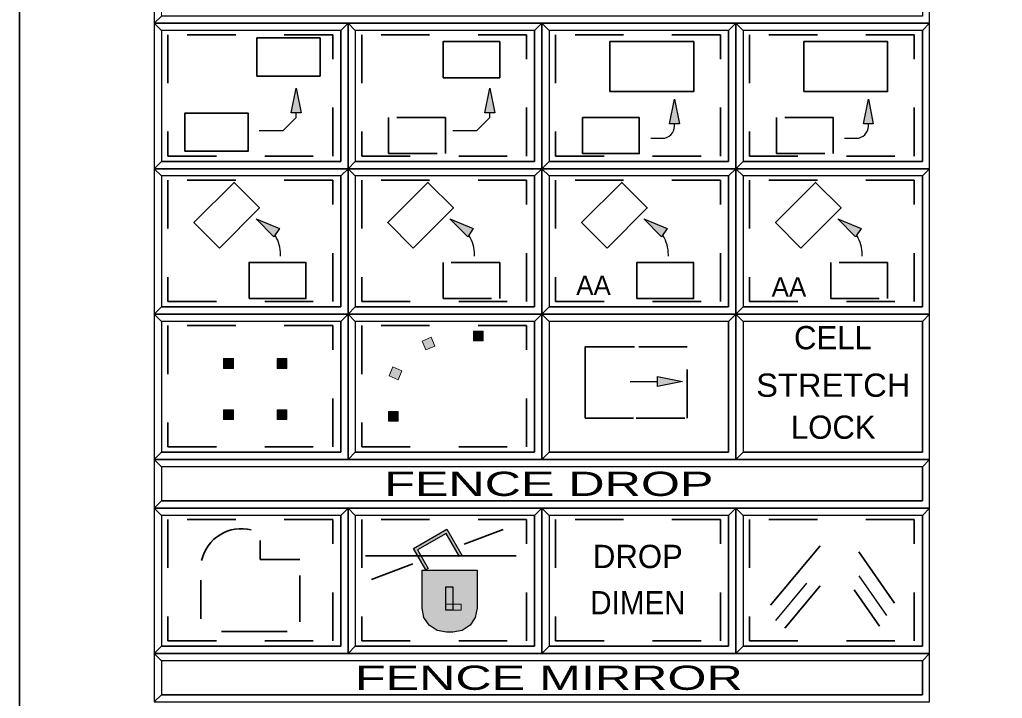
# Model space of a CAD drawing. Extents: x 95906.9 to 95918.9, y 90964.8 to 90972.9.
# Drawn here: x 95906.855 to 95908.882, y 90966.169 to 90967.569 of the extents above; entities that cross this region are included whole.
import ezdxf
from ezdxf.enums import TextEntityAlignment as Align

# ---------------------------------------------------------------- set-up
doc = ezdxf.new("R2010")
doc.units = 0
doc.header["$LTSCALE"] = 0.019
for name, pattern in [('DOT_DASHED', [7.7, 5, -1.2, 0.3, -1.2]), ('DOTTED', [1.5, 0.3, -1.2]), ('MEDIUM_DASHED', [4.5, 3, -1.5])]:
    doc.linetypes.add(name, pattern=pattern)
for name, color, linetype, lineweight in [('1', 7, 'Continuous', 25), ('11', 7, 'Continuous', 25), ('12', 7, 'Continuous', 25), ('18', 7, 'Continuous', 25), ('2', 7, 'Continuous', 13), ('3', 7, 'Continuous', 25), ('4', 7, 'Continuous', 35), ('6', 7, 'Continuous', 35), ('7', 7, 'Continuous', 35)]:
    doc.layers.add(name, color=color, linetype=linetype, lineweight=lineweight)

msp = doc.modelspace()

# ---------------------------------------------------------------- hatches: boundary and pattern name
at = {"layer": '6'}
for points in [[(95907.4251, 90967.4281), (95907.4353, 90967.3769), (95907.4149, 90967.3769)], [(95907.8251, 90967.4281), (95907.8353, 90967.3769), (95907.8149, 90967.3769)], [(95908.2059, 90967.4052), (95908.2161, 90967.354), (95908.1957, 90967.354)], [(95908.6059, 90967.4052), (95908.6161, 90967.354), (95908.5957, 90967.354)], [(95907.3426, 90967.1585), (95907.3908, 90967.1384), (95907.3793, 90967.1214)], [(95907.7426, 90967.1585), (95907.7908, 90967.1384), (95907.7793, 90967.1214)], [(95908.1426, 90967.1585), (95908.1908, 90967.1384), (95908.1793, 90967.1214)], [(95908.5426, 90967.1585), (95908.5908, 90967.1384), (95908.5793, 90967.1214)], [(95907.7115, 90966.8955), (95907.7038, 90966.914), (95907.6854, 90966.9063), (95907.693, 90966.8878)], [(95907.7912, 90966.9067), (95907.8112, 90966.9067), (95907.8112, 90966.9267), (95907.7912, 90966.9267)], [(95907.2757, 90966.8499), (95907.2957, 90966.8499), (95907.2957, 90966.8699), (95907.2757, 90966.8699)], [(95907.3861, 90966.8499), (95907.4061, 90966.8499), (95907.4061, 90966.8699), (95907.3861, 90966.8699)], [(95907.6432, 90966.845), (95907.6247, 90966.8527), (95907.6171, 90966.8342), (95907.6355, 90966.8265)], [(95908.2221, 90966.823), (95908.1709, 90966.8128), (95908.1709, 90966.8332)], [(95907.2757, 90966.7446), (95907.2957, 90966.7446), (95907.2957, 90966.7646), (95907.2757, 90966.7646)], [(95907.3861, 90966.7446), (95907.4061, 90966.7446), (95907.4061, 90966.7646), (95907.3861, 90966.7646)], [(95907.636, 90966.7408), (95907.636, 90966.7608), (95907.616, 90966.7608), (95907.616, 90966.7408)], [(95907.693, 90966.4345), (95907.6677, 90966.4783), (95907.7363, 90966.5179), (95907.767, 90966.4648), (95907.7623, 90966.4621), (95907.7351, 90966.5095), (95907.6755, 90966.4753), (95907.6975, 90966.4371)], [(95907.6852, 90966.3554), (95907.6852, 90966.4338), (95907.7987, 90966.4338), (95907.7987, 90966.3554), (95907.7949, 90966.3363), (95907.7841, 90966.32), (95907.7678, 90966.3092), (95907.7487, 90966.3054), (95907.7352, 90966.3054), (95907.7161, 90966.3092), (95907.6998, 90966.32), (95907.689, 90966.3363)], [(95907.7342, 90966.3989), (95907.7484, 90966.3989), (95907.7484, 90966.3508), (95907.7342, 90966.3508)], [(95907.7342, 90966.3508), (95907.7655, 90966.3508), (95907.7655, 90966.3633), (95907.7342, 90966.3633)]]:
    msp.add_hatch(color=256, dxfattribs=at).paths.add_polyline_path(points)

# ---------------------------------------------------------------- linework, layer by layer
at = {"layer": '1'}
for points in [[(95907.1323, 90967.5617), (95908.7323, 90967.5617), (95908.7323, 90967.6617), (95907.1323, 90967.6617)], [(95907.1323, 90967.2617), (95907.5323, 90967.2617), (95907.5323, 90967.5617), (95907.1323, 90967.5617)], [(95907.5323, 90967.2617), (95907.9323, 90967.2617), (95907.9323, 90967.5617), (95907.5323, 90967.5617)], [(95907.9323, 90967.2617), (95908.3323, 90967.2617), (95908.3323, 90967.5617), (95907.9323, 90967.5617)], [(95908.3323, 90967.2617), (95908.7323, 90967.2617), (95908.7323, 90967.5617), (95908.3323, 90967.5617)], [(95907.1323, 90966.9617), (95907.5323, 90966.9617), (95907.5323, 90967.2617), (95907.1323, 90967.2617)], [(95907.5323, 90966.9617), (95907.9323, 90966.9617), (95907.9323, 90967.2617), (95907.5323, 90967.2617)], [(95907.9323, 90966.9617), (95908.3323, 90966.9617), (95908.3323, 90967.2617), (95907.9323, 90967.2617)], [(95908.3323, 90966.9617), (95908.7323, 90966.9617), (95908.7323, 90967.2617), (95908.3323, 90967.2617)], [(95907.1323, 90966.6617), (95907.5323, 90966.6617), (95907.5323, 90966.9617), (95907.1323, 90966.9617)], [(95907.5323, 90966.6617), (95907.9323, 90966.6617), (95907.9323, 90966.9617), (95907.5323, 90966.9617)], [(95907.9323, 90966.6617), (95908.3323, 90966.6617), (95908.3323, 90966.9617), (95907.9323, 90966.9617)], [(95908.3323, 90966.6617), (95908.7323, 90966.6617), (95908.7323, 90966.9617), (95908.3323, 90966.9617)], [(95907.1323, 90966.5617), (95908.7323, 90966.5617), (95908.7323, 90966.6617), (95907.1323, 90966.6617)], [(95907.1323, 90966.2617), (95907.5323, 90966.2617), (95907.5323, 90966.5617), (95907.1323, 90966.5617)], [(95907.5323, 90966.2617), (95907.9323, 90966.2617), (95907.9323, 90966.5617), (95907.5323, 90966.5617)], [(95907.9323, 90966.2617), (95908.3323, 90966.2617), (95908.3323, 90966.5617), (95907.9323, 90966.5617)], [(95908.3323, 90966.2617), (95908.7323, 90966.2617), (95908.7323, 90966.5617), (95908.3323, 90966.5617)], [(95907.1323, 90966.1617), (95908.7323, 90966.1617), (95908.7323, 90966.2617), (95907.1323, 90966.2617)]]:
    msp.add_lwpolyline(points, close=True, dxfattribs=at)
at = {"layer": '11'}
for points in [[(95907.1473, 90967.2767), (95907.5173, 90967.2767), (95907.5173, 90967.5467), (95907.1473, 90967.5467)], [(95907.5473, 90967.2767), (95907.9173, 90967.2767), (95907.9173, 90967.5467), (95907.5473, 90967.5467)], [(95907.9473, 90967.2767), (95908.3173, 90967.2767), (95908.3173, 90967.5467), (95907.9473, 90967.5467)], [(95908.3473, 90967.2767), (95908.7173, 90967.2767), (95908.7173, 90967.5467), (95908.3473, 90967.5467)], [(95907.1473, 90966.9767), (95907.5173, 90966.9767), (95907.5173, 90967.2467), (95907.1473, 90967.2467)], [(95907.5473, 90966.9767), (95907.9173, 90966.9767), (95907.9173, 90967.2467), (95907.5473, 90967.2467)], [(95907.9473, 90966.9767), (95908.3173, 90966.9767), (95908.3173, 90967.2467), (95907.9473, 90967.2467)], [(95908.3473, 90966.9767), (95908.7173, 90966.9767), (95908.7173, 90967.2467), (95908.3473, 90967.2467)], [(95907.1473, 90966.6767), (95907.5173, 90966.6767), (95907.5173, 90966.9467), (95907.1473, 90966.9467)], [(95907.5473, 90966.6767), (95907.9173, 90966.6767), (95907.9173, 90966.9467), (95907.5473, 90966.9467)], [(95907.9473, 90966.6767), (95908.3173, 90966.6767), (95908.3173, 90966.9467), (95907.9473, 90966.9467)], [(95908.3473, 90966.6767), (95908.7173, 90966.6767), (95908.7173, 90966.9467), (95908.3473, 90966.9467)], [(95907.1473, 90966.2767), (95907.5173, 90966.2767), (95907.5173, 90966.5467), (95907.1473, 90966.5467)], [(95907.5473, 90966.2767), (95907.9173, 90966.2767), (95907.9173, 90966.5467), (95907.5473, 90966.5467)], [(95907.9473, 90966.2767), (95908.3173, 90966.2767), (95908.3173, 90966.5467), (95907.9473, 90966.5467)], [(95908.3473, 90966.2767), (95908.7173, 90966.2767), (95908.7173, 90966.5467), (95908.3473, 90966.5467)]]:
    msp.add_lwpolyline(points, close=True, dxfattribs=at)
at = {"layer": '12'}
msp.add_lwpolyline([(95907.1473, 90966.2767), (95907.5173, 90966.2767), (95907.5173, 90966.5467), (95907.1473, 90966.5467)], close=True, dxfattribs=at)
at = {"layer": '18'}
for points in [[(95907.1473, 90966.5767), (95908.7173, 90966.5767), (95908.7173, 90966.6467), (95907.1473, 90966.6467)], [(95907.1473, 90966.1767), (95908.7173, 90966.1767), (95908.7173, 90966.2467), (95907.1473, 90966.2467)]]:
    msp.add_lwpolyline(points, close=True, dxfattribs=at)
at = {"layer": '2'}
for points in [[(95907.1323, 90967.6617), (95907.1323, 90967.5617), (95907.1473, 90967.5767), (95907.1473, 90967.6467), (95908.7173, 90967.6467), (95908.7323, 90967.6617)], [(95907.1323, 90967.5617), (95907.1323, 90967.2617), (95907.1473, 90967.2767), (95907.1473, 90967.5467), (95907.5173, 90967.5467), (95907.5323, 90967.5617)], [(95907.5323, 90967.5617), (95907.5323, 90967.2617), (95907.5473, 90967.2767), (95907.5473, 90967.5467), (95907.9173, 90967.5467), (95907.9323, 90967.5617)], [(95907.9323, 90967.5617), (95907.9323, 90967.2617), (95907.9473, 90967.2767), (95907.9473, 90967.5467), (95908.3173, 90967.5467), (95908.3323, 90967.5617)], [(95908.3323, 90967.5617), (95908.3323, 90967.2617), (95908.3473, 90967.2767), (95908.3473, 90967.5467), (95908.7173, 90967.5467), (95908.7323, 90967.5617)], [(95907.1323, 90967.2617), (95907.1323, 90966.9617), (95907.1473, 90966.9767), (95907.1473, 90967.2467), (95907.5173, 90967.2467), (95907.5323, 90967.2617)], [(95907.5323, 90967.2617), (95907.5323, 90966.9617), (95907.5473, 90966.9767), (95907.5473, 90967.2467), (95907.9173, 90967.2467), (95907.9323, 90967.2617)], [(95907.9323, 90967.2617), (95907.9323, 90966.9617), (95907.9473, 90966.9767), (95907.9473, 90967.2467), (95908.3173, 90967.2467), (95908.3323, 90967.2617)], [(95908.3323, 90967.2617), (95908.3323, 90966.9617), (95908.3473, 90966.9767), (95908.3473, 90967.2467), (95908.7173, 90967.2467), (95908.7323, 90967.2617)], [(95907.1323, 90966.9617), (95907.1323, 90966.6617), (95907.1473, 90966.6767), (95907.1473, 90966.9467), (95907.5173, 90966.9467), (95907.5323, 90966.9617)], [(95907.5323, 90966.9617), (95907.5323, 90966.6617), (95907.5473, 90966.6767), (95907.5473, 90966.9467), (95907.9173, 90966.9467), (95907.9323, 90966.9617)], [(95907.9323, 90966.9617), (95907.9323, 90966.6617), (95907.9473, 90966.6767), (95907.9473, 90966.9467), (95908.3173, 90966.9467), (95908.3323, 90966.9617)], [(95908.3323, 90966.9617), (95908.3323, 90966.6617), (95908.3473, 90966.6767), (95908.3473, 90966.9467), (95908.7173, 90966.9467), (95908.7323, 90966.9617)], [(95907.1323, 90966.6617), (95907.1323, 90966.5617), (95907.1473, 90966.5767), (95907.1473, 90966.6467), (95908.7173, 90966.6467), (95908.7323, 90966.6617)], [(95907.1323, 90966.5617), (95907.1323, 90966.2617), (95907.1473, 90966.2767), (95907.1473, 90966.5467), (95907.5173, 90966.5467), (95907.5323, 90966.5617)], [(95907.5323, 90966.5617), (95907.5323, 90966.2617), (95907.5473, 90966.2767), (95907.5473, 90966.5467), (95907.9173, 90966.5467), (95907.9323, 90966.5617)], [(95907.9323, 90966.5617), (95907.9323, 90966.2617), (95907.9473, 90966.2767), (95907.9473, 90966.5467), (95908.3173, 90966.5467), (95908.3323, 90966.5617)], [(95908.3323, 90966.5617), (95908.3323, 90966.2617), (95908.3473, 90966.2767), (95908.3473, 90966.5467), (95908.7173, 90966.5467), (95908.7323, 90966.5617)], [(95907.1323, 90966.2617), (95907.1323, 90966.1617), (95907.1473, 90966.1767), (95907.1473, 90966.2467), (95908.7173, 90966.2467), (95908.7323, 90966.2617)]]:
    msp.add_lwpolyline(points, close=True, dxfattribs=at)
at = {"layer": '3'}
for points in [[(95907.1323, 90967.5617), (95908.7323, 90967.5617), (95908.7323, 90967.6617), (95908.7173, 90967.6467), (95908.7173, 90967.5767), (95907.1473, 90967.5767)], [(95907.1323, 90967.2617), (95907.5323, 90967.2617), (95907.5323, 90967.5617), (95907.5173, 90967.5467), (95907.5173, 90967.2767), (95907.1473, 90967.2767)], [(95907.5323, 90967.2617), (95907.9323, 90967.2617), (95907.9323, 90967.5617), (95907.9173, 90967.5467), (95907.9173, 90967.2767), (95907.5473, 90967.2767)], [(95907.9323, 90967.2617), (95908.3323, 90967.2617), (95908.3323, 90967.5617), (95908.3173, 90967.5467), (95908.3173, 90967.2767), (95907.9473, 90967.2767)], [(95908.3323, 90967.2617), (95908.7323, 90967.2617), (95908.7323, 90967.5617), (95908.7173, 90967.5467), (95908.7173, 90967.2767), (95908.3473, 90967.2767)], [(95907.1323, 90966.9617), (95907.5323, 90966.9617), (95907.5323, 90967.2617), (95907.5173, 90967.2467), (95907.5173, 90966.9767), (95907.1473, 90966.9767)], [(95907.5323, 90966.9617), (95907.9323, 90966.9617), (95907.9323, 90967.2617), (95907.9173, 90967.2467), (95907.9173, 90966.9767), (95907.5473, 90966.9767)], [(95907.9323, 90966.9617), (95908.3323, 90966.9617), (95908.3323, 90967.2617), (95908.3173, 90967.2467), (95908.3173, 90966.9767), (95907.9473, 90966.9767)], [(95908.3323, 90966.9617), (95908.7323, 90966.9617), (95908.7323, 90967.2617), (95908.7173, 90967.2467), (95908.7173, 90966.9767), (95908.3473, 90966.9767)], [(95907.1323, 90966.6617), (95907.5323, 90966.6617), (95907.5323, 90966.9617), (95907.5173, 90966.9467), (95907.5173, 90966.6767), (95907.1473, 90966.6767)], [(95907.5323, 90966.6617), (95907.9323, 90966.6617), (95907.9323, 90966.9617), (95907.9173, 90966.9467), (95907.9173, 90966.6767), (95907.5473, 90966.6767)], [(95907.9323, 90966.6617), (95908.3323, 90966.6617), (95908.3323, 90966.9617), (95908.3173, 90966.9467), (95908.3173, 90966.6767), (95907.9473, 90966.6767)], [(95908.3323, 90966.6617), (95908.7323, 90966.6617), (95908.7323, 90966.9617), (95908.7173, 90966.9467), (95908.7173, 90966.6767), (95908.3473, 90966.6767)], [(95907.1323, 90966.5617), (95908.7323, 90966.5617), (95908.7323, 90966.6617), (95908.7173, 90966.6467), (95908.7173, 90966.5767), (95907.1473, 90966.5767)], [(95907.1323, 90966.2617), (95907.5323, 90966.2617), (95907.5323, 90966.5617), (95907.5173, 90966.5467), (95907.5173, 90966.2767), (95907.1473, 90966.2767)], [(95907.5323, 90966.2617), (95907.9323, 90966.2617), (95907.9323, 90966.5617), (95907.9173, 90966.5467), (95907.9173, 90966.2767), (95907.5473, 90966.2767)], [(95907.9323, 90966.2617), (95908.3323, 90966.2617), (95908.3323, 90966.5617), (95908.3173, 90966.5467), (95908.3173, 90966.2767), (95907.9473, 90966.2767)], [(95908.3323, 90966.2617), (95908.7323, 90966.2617), (95908.7323, 90966.5617), (95908.7173, 90966.5467), (95908.7173, 90966.2767), (95908.3473, 90966.2767)], [(95907.1323, 90966.1617), (95908.7323, 90966.1617), (95908.7323, 90966.2617), (95908.7173, 90966.2467), (95908.7173, 90966.1767), (95907.1473, 90966.1767)]]:
    msp.add_lwpolyline(points, close=True, dxfattribs=at)
at = {"layer": '4'}
for p, q in [((95907.1473, 90967.5467), (95907.1323, 90967.5617)), ((95907.5473, 90967.5467), (95907.5323, 90967.5617)), ((95907.9473, 90967.5467), (95907.9323, 90967.5617)), ((95908.3473, 90967.5467), (95908.3323, 90967.5617)), ((95907.1473, 90967.2467), (95907.1323, 90967.2617)), ((95907.5473, 90967.2467), (95907.5323, 90967.2617)), ((95907.9473, 90967.2467), (95907.9323, 90967.2617)), ((95908.3473, 90967.2467), (95908.3323, 90967.2617)), ((95907.1473, 90966.9467), (95907.1323, 90966.9617)), ((95907.5473, 90966.9467), (95907.5323, 90966.9617)), ((95907.9473, 90966.9467), (95907.9323, 90966.9617)), ((95908.3473, 90966.9467), (95908.3323, 90966.9617)), ((95907.1473, 90966.6467), (95907.1323, 90966.6617)), ((95907.1473, 90966.5467), (95907.1323, 90966.5617)), ((95907.5473, 90966.5467), (95907.5323, 90966.5617)), ((95907.9473, 90966.5467), (95907.9323, 90966.5617)), ((95908.3473, 90966.5467), (95908.3323, 90966.5617)), ((95907.1473, 90966.2467), (95907.1323, 90966.2617))]:
    msp.add_line(p, q, dxfattribs=at)
at = {"layer": '6', "lineweight": 25}
for p, q in [((95907.4353, 90967.3769), (95907.4149, 90967.3769)), ((95907.8353, 90967.3769), (95907.8149, 90967.3769)), ((95908.2059, 90967.3495), (95908.2059, 90967.354)), ((95908.6059, 90967.3495), (95908.6059, 90967.354)), ((95908.1569, 90967.3245), (95908.1809, 90967.3245)), ((95908.5569, 90967.3245), (95908.5809, 90967.3245)), ((95907.3933, 90967.081), (95907.3933, 90967.0844)), ((95907.7933, 90967.081), (95907.7933, 90967.0844)), ((95908.1933, 90967.081), (95908.1933, 90967.0844)), ((95908.1933, 90967.081), (95908.1933, 90967.0844)), ((95908.5933, 90967.081), (95908.5933, 90967.0844)), ((95908.5933, 90967.081), (95908.5933, 90967.0844)), ((95908.1146, 90966.823), (95908.1709, 90966.823))]:
    msp.add_line(p, q, dxfattribs=at)
at = {"layer": '6'}
for p, q in [((95907.8521, 90966.5178), (95907.7717, 90966.4871)), ((95908.404, 90966.3615), (95908.5067, 90966.4839)), ((95908.5862, 90966.4713), (95908.6601, 90966.3657)), ((95907.5685, 90966.4635), (95907.8792, 90966.4635)), ((95907.5804, 90966.4142), (95907.6662, 90966.4469)), ((95907.2284, 90966.3332), (95907.2284, 90966.4131)), ((95907.4328, 90966.4223), (95907.4328, 90966.327)), ((95908.4335, 90966.3142), (95908.5067, 90966.4015)), ((95908.5763, 90966.3931), (95908.629, 90966.3178)), ((95907.4067, 90966.3071), (95907.2714, 90966.3071))]:
    msp.add_line(p, q, dxfattribs=at)
at = {"layer": '6', "linetype": 'DOT_DASHED', "lineweight": 25}
for p, q in [((95908.4147, 90966.3299), (95908.5067, 90966.4396)), ((95908.5862, 90966.4217), (95908.6491, 90966.3319))]:
    msp.add_line(p, q, dxfattribs=at)
at = {"layer": '6', "linetype": 'DOTTED'}
for points in [[(95907.5007, 90967.5382), (95907.1606, 90967.5382), (95907.1606, 90967.2878), (95907.5007, 90967.2878)], [(95907.9007, 90967.5382), (95907.5606, 90967.5382), (95907.5606, 90967.2878), (95907.9007, 90967.2878)], [(95908.3007, 90967.5382), (95907.9606, 90967.5382), (95907.9606, 90967.2878), (95908.3007, 90967.2878)], [(95908.7007, 90967.5382), (95908.3606, 90967.5382), (95908.3606, 90967.2878), (95908.7007, 90967.2878)], [(95907.5007, 90967.2382), (95907.1606, 90967.2382), (95907.1606, 90966.9878), (95907.5007, 90966.9878)], [(95907.9007, 90967.2382), (95907.5606, 90967.2382), (95907.5606, 90966.9878), (95907.9007, 90966.9878)], [(95908.3007, 90967.2382), (95907.9606, 90967.2382), (95907.9606, 90966.9878), (95908.3007, 90966.9878)], [(95908.7007, 90967.2382), (95908.3606, 90967.2382), (95908.3606, 90966.9878), (95908.7007, 90966.9878)], [(95907.5007, 90966.9382), (95907.1606, 90966.9382), (95907.1606, 90966.6878), (95907.5007, 90966.6878)], [(95907.9007, 90966.9382), (95907.5606, 90966.9382), (95907.5606, 90966.6878), (95907.9007, 90966.6878)], [(95907.5007, 90966.5382), (95907.1606, 90966.5382), (95907.1606, 90966.2878), (95907.5007, 90966.2878)], [(95907.9007, 90966.5382), (95907.5606, 90966.5382), (95907.5606, 90966.2878), (95907.9007, 90966.2878)], [(95908.3007, 90966.5382), (95907.9606, 90966.5382), (95907.9606, 90966.2878), (95908.3007, 90966.2878)], [(95908.7007, 90966.5382), (95908.3606, 90966.5382), (95908.3606, 90966.2878), (95908.7007, 90966.2878)]]:
    msp.add_lwpolyline(points, close=True, dxfattribs=at)
at = {"layer": '6'}
for points in [[(95907.3442, 90967.4528), (95907.4747, 90967.4528), (95907.4747, 90967.5315), (95907.3442, 90967.5315)], [(95907.7284, 90967.4495), (95907.8455, 90967.4495), (95907.8455, 90967.5238), (95907.7284, 90967.5238)], [(95908.0724, 90967.421), (95908.2455, 90967.421), (95908.2455, 90967.5238), (95908.0724, 90967.5238)], [(95908.4724, 90967.421), (95908.6455, 90967.421), (95908.6455, 90967.5238), (95908.4724, 90967.5238)], [(95907.1957, 90967.2977), (95907.3262, 90967.2977), (95907.3262, 90967.3764), (95907.1957, 90967.3764)], [(95908.0161, 90967.2929), (95908.1332, 90967.2929), (95908.1332, 90967.3672), (95908.0161, 90967.3672)], [(95907.2668, 90967.0981), (95907.3496, 90967.1809), (95907.2971, 90967.2334), (95907.2143, 90967.1506)], [(95907.6668, 90967.0981), (95907.7496, 90967.1809), (95907.6971, 90967.2334), (95907.6143, 90967.1506)], [(95908.0668, 90967.0981), (95908.1496, 90967.1809), (95908.0971, 90967.2334), (95908.0143, 90967.1506)], [(95908.4668, 90967.0981), (95908.5496, 90967.1809), (95908.4971, 90967.2334), (95908.4143, 90967.1506)], [(95907.3283, 90966.994), (95907.4454, 90966.994), (95907.4454, 90967.0683), (95907.3283, 90967.0683)], [(95908.1283, 90966.994), (95908.2454, 90966.994), (95908.2454, 90967.0683), (95908.1283, 90967.0683)]]:
    msp.add_lwpolyline(points, close=True, dxfattribs=at)
at = {"layer": '6', "lineweight": 25}
for points in [[(95907.4251, 90967.4281), (95907.4353, 90967.3769), (95907.4149, 90967.3769)], [(95907.8251, 90967.4281), (95907.8353, 90967.3769), (95907.8149, 90967.3769)], [(95908.2059, 90967.4052), (95908.2161, 90967.354), (95908.1957, 90967.354)], [(95908.6059, 90967.4052), (95908.6161, 90967.354), (95908.5957, 90967.354)], [(95907.3426, 90967.1585), (95907.3908, 90967.1384), (95907.3793, 90967.1214)], [(95907.7426, 90967.1585), (95907.7908, 90967.1384), (95907.7793, 90967.1214)], [(95908.1426, 90967.1585), (95908.1908, 90967.1384), (95908.1793, 90967.1214)], [(95908.5426, 90967.1585), (95908.5908, 90967.1384), (95908.5793, 90967.1214)], [(95908.2221, 90966.823), (95908.1709, 90966.8128), (95908.1709, 90966.8332)], [(95907.693, 90966.4345), (95907.6677, 90966.4783), (95907.7363, 90966.5179), (95907.767, 90966.4648), (95907.7623, 90966.4621), (95907.7351, 90966.5095), (95907.6755, 90966.4753), (95907.6975, 90966.4371)], [(95907.6852, 90966.3554), (95907.6852, 90966.4338), (95907.7987, 90966.4338), (95907.7987, 90966.3554), (95907.7949, 90966.3363), (95907.7841, 90966.32), (95907.7678, 90966.3092), (95907.7487, 90966.3054), (95907.7352, 90966.3054), (95907.7161, 90966.3092), (95907.6998, 90966.32), (95907.689, 90966.3363)], [(95907.7342, 90966.3989), (95907.7484, 90966.3989), (95907.7484, 90966.3508), (95907.7342, 90966.3508)]]:
    msp.add_lwpolyline(points, close=True, dxfattribs=at)
for points in [[(95907.3487, 90967.3404), (95907.3982, 90967.3404), (95907.4251, 90967.3673), (95907.4251, 90967.3769)], [(95907.7487, 90967.3404), (95907.7982, 90967.3404), (95907.8251, 90967.3673), (95907.8251, 90967.3769)]]:
    msp.add_lwpolyline(points, dxfattribs=at)
at = {"layer": '6', "linetype": 'MEDIUM_DASHED'}
for points in [[(95907.6161, 90967.2929), (95907.7332, 90967.2929), (95907.7332, 90967.3672), (95907.6161, 90967.3672)], [(95908.4161, 90967.2929), (95908.5332, 90967.2929), (95908.5332, 90967.3672), (95908.4161, 90967.3672)], [(95907.7283, 90966.994), (95907.8454, 90966.994), (95907.8454, 90967.0683), (95907.7283, 90967.0683)], [(95908.5283, 90966.994), (95908.6454, 90966.994), (95908.6454, 90967.0683), (95908.5283, 90967.0683)]]:
    msp.add_lwpolyline(points, close=True, dxfattribs=at)
at = {"layer": '6', "lineweight": 13}
for points in [[(95907.7115, 90966.8955), (95907.7038, 90966.914), (95907.6854, 90966.9063), (95907.693, 90966.8878)], [(95907.7912, 90966.9067), (95907.8112, 90966.9067), (95907.8112, 90966.9267), (95907.7912, 90966.9267)], [(95907.2757, 90966.8499), (95907.2957, 90966.8499), (95907.2957, 90966.8699), (95907.2757, 90966.8699)], [(95907.3861, 90966.8499), (95907.4061, 90966.8499), (95907.4061, 90966.8699), (95907.3861, 90966.8699)], [(95907.6432, 90966.845), (95907.6247, 90966.8527), (95907.6171, 90966.8342), (95907.6355, 90966.8265)], [(95907.2757, 90966.7446), (95907.2957, 90966.7446), (95907.2957, 90966.7646), (95907.2757, 90966.7646)], [(95907.3861, 90966.7446), (95907.4061, 90966.7446), (95907.4061, 90966.7646), (95907.3861, 90966.7646)], [(95907.636, 90966.7408), (95907.636, 90966.7608), (95907.616, 90966.7608), (95907.616, 90966.7408)], [(95907.7342, 90966.3508), (95907.7655, 90966.3508), (95907.7655, 90966.3633), (95907.7342, 90966.3633)]]:
    msp.add_lwpolyline(points, close=True, dxfattribs=at)
at = {"layer": '6'}
for points in [[(95908.1231, 90966.8944), (95908.0219, 90966.8944), (95908.0219, 90966.7474), (95908.1214, 90966.7474)], [(95907.4328, 90966.4557), (95907.3513, 90966.4557), (95907.3513, 90966.4946)]]:
    msp.add_lwpolyline(points, dxfattribs=at)
at = {"layer": '6', "linetype": 'DOTTED'}
msp.add_lwpolyline([(95908.127, 90966.7474), (95908.232, 90966.7474), (95908.232, 90966.8944), (95908.1271, 90966.8944)], dxfattribs=at)
at = {"layer": '6', "lineweight": 25}
for centre, radius, start, end in [((95908.1809, 90967.3495), 0.025, 270, 0), ((95908.5809, 90967.3495), 0.025, 270, 0), ((95907.3183, 90967.0844), 0.075, 0, 31.2093), ((95907.7183, 90967.0844), 0.075, 0, 31.2093), ((95908.1183, 90967.0844), 0.075, 0, 31.2093), ((95908.5183, 90967.0844), 0.075, 0, 31.2093)]:
    msp.add_arc(centre, radius, start, end, dxfattribs=at)
at = {"layer": '6'}
msp.add_arc((95907.3121, 90966.4354), 0.0838, 75.8303, 167.4043, dxfattribs=at)
at = {"layer": '7'}
msp.add_lwpolyline([(95906.8548, 90972.8617), (95918.8548, 90972.8617), (95918.8548, 90964.7617), (95906.8548, 90964.7617)], close=True, dxfattribs=at)

# ---------------------------------------------------------------- texts
at = {"layer": '6'}
for s, height, p in [('AA', 0.04, (95908.0388, 90967.0012)), ('AA', 0.04, (95908.442, 90966.998)), ('CELL', 0.048, (95908.5328, 90966.8892)), ('LOCK', 0.048, (95908.5335, 90966.7046)), ('DROP', 0.048, (95908.1303, 90966.4379))]:
    msp.add_text(s, height=height, dxfattribs=at).set_placement(p, align=Align.CENTER)
for s, width, p in [('STRETCH', 1.05, (95908.5335, 90966.7912)), ('DIMEN', 0.95, (95908.1303, 90966.3425))]:
    msp.add_text(s, height=0.048, dxfattribs=dict(at, width=width)).set_placement(p, align=Align.CENTER)
at = {"layer": '7', "width": 1.55}
for s, p in [('       FENCE DROP      ', (95907.9322, 90966.5867)), ('      FENCE MIRROR     ', (95907.9322, 90966.1867))]:
    msp.add_text(s, height=0.04999, dxfattribs=at).set_placement(p, align=Align.CENTER)

doc.saveas('drawing.dxf')
